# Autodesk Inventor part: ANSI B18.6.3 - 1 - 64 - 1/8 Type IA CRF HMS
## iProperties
IsCustomPart: 0
Created: 2008-01
Part Number: ANSI B18.6.3 - 1 - 64 - 1/8 Type IA CRF HMS
Material: Steel, Mild
Description: Cross Recessed Fillister Head Machine Screw - Type IA
Document SubType Name: Modeling
Standard: ANSI B18.6.3
Standard Revision: 2003
Standards Organization: ANSI
Language: en-US
Size Designation: 1 - 64 - 1/8
Categories: <MemberInstance><Categories><Category DisplayName="Fasteners" InternalName="e4da775c-781d-43d5-af7c-5136215cf5a6" Mnemonic="FSTN"><Category DisplayName="Bolts"
Density: 1 g/cm^3
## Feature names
1. Body [Revolution]
2. Slot [Extrusion]
3. Cut [Revolution]
4. Star Cut [Extrusion]
5. Fillet1
6. Chamfer
